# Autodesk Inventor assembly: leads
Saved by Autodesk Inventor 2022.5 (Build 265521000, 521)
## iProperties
Created: 2024-12
Part Number: leads
Document SubType Name: Assembly
Designer: AdminForWorker
Title: leads
Author: AdminForWorker
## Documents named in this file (3)
- c:\worker\convert-fusion-r05-cosv3\tmp\job-1\35\temp\files\545dca92-a972-481a-9197-dd1a1176500e\leads_1.iam
- c:\worker\convert-fusion-r05-cosv3\tmp\job-1\35\temp\files\545dca92-a972-481a-9197-dd1a1176500e\top_lead.ipt
- c:\worker\convert-fusion-r05-cosv3\tmp\job-1\35\temp\files\545dca92-a972-481a-9197-dd1a1176500e\bottom_lead.ipt
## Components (8 placed, 2 different names)
1. top_lead:1
2. top_lead:5
3. top_lead:6
4. top_lead:7
5. bottom_lead:1
6. bottom_lead:8
7. bottom_lead:9
8. bottom_lead:10
